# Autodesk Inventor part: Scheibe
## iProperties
Title: Scheibe
Company: Mayer & Mueller Schaltgeräte AG
Created: 2006-01
Part Number: T 358 245
Material: PA6.6
Description: Scheibe
Vendor: Autodesk Inc.
Document SubType Name: Modeling
Standard: DIN 671
Designer: I.Baliuc
Size Designation: 35 - 5
Density: 1.13 g/cm^3
Zweck: DC - Schalter
Abmessung: Ø35 - 5
Author: T.Messerschmitt
Revision Number: 358245
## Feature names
1. Körper [Extrusion]
2. Bohrung1 [Hole]
3. Rundung1 [Fillet]
